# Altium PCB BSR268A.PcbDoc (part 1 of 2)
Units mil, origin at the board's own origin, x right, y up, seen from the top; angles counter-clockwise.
Board outline 3689.1 x 2409.61 mil, 4 copper layers (Top Layer, Signal Layer 1, Signal Layer 2, Bottom Layer), stack 60.312 mil thick; 90 components, 29 nets, 160 pads, 335 vias.
Unrouted connection lines stored in the file: 5.
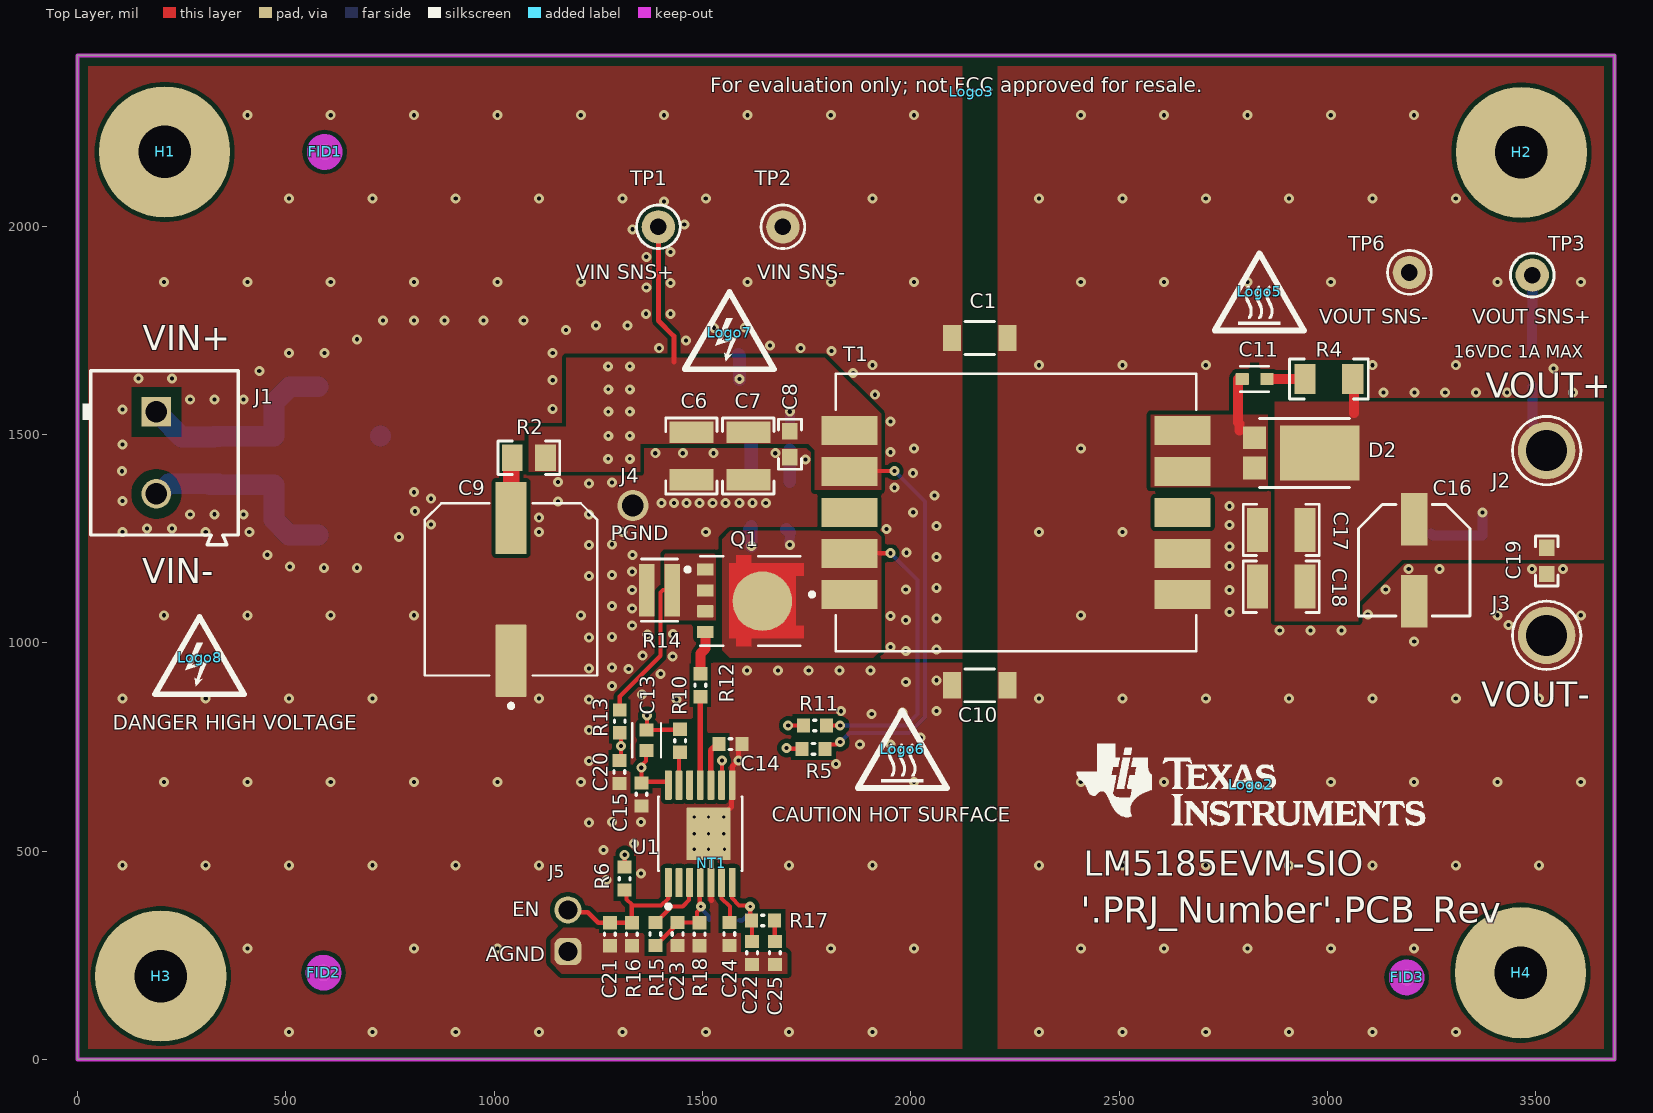
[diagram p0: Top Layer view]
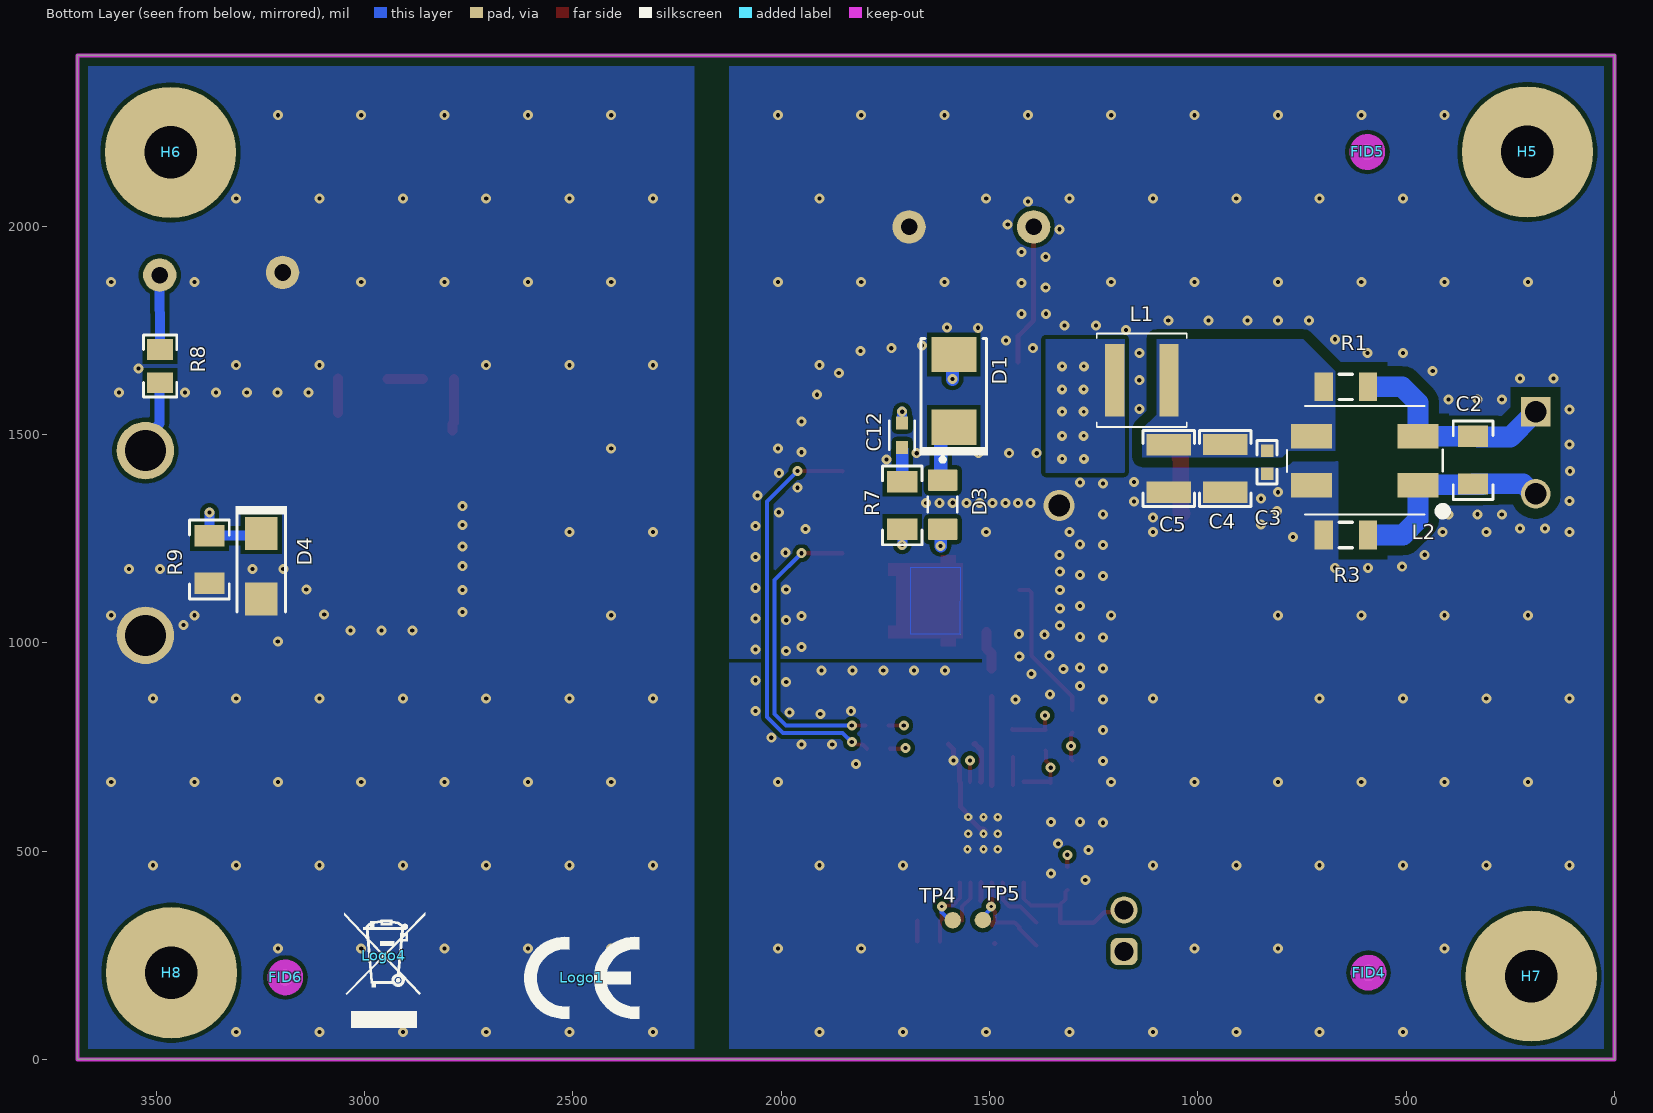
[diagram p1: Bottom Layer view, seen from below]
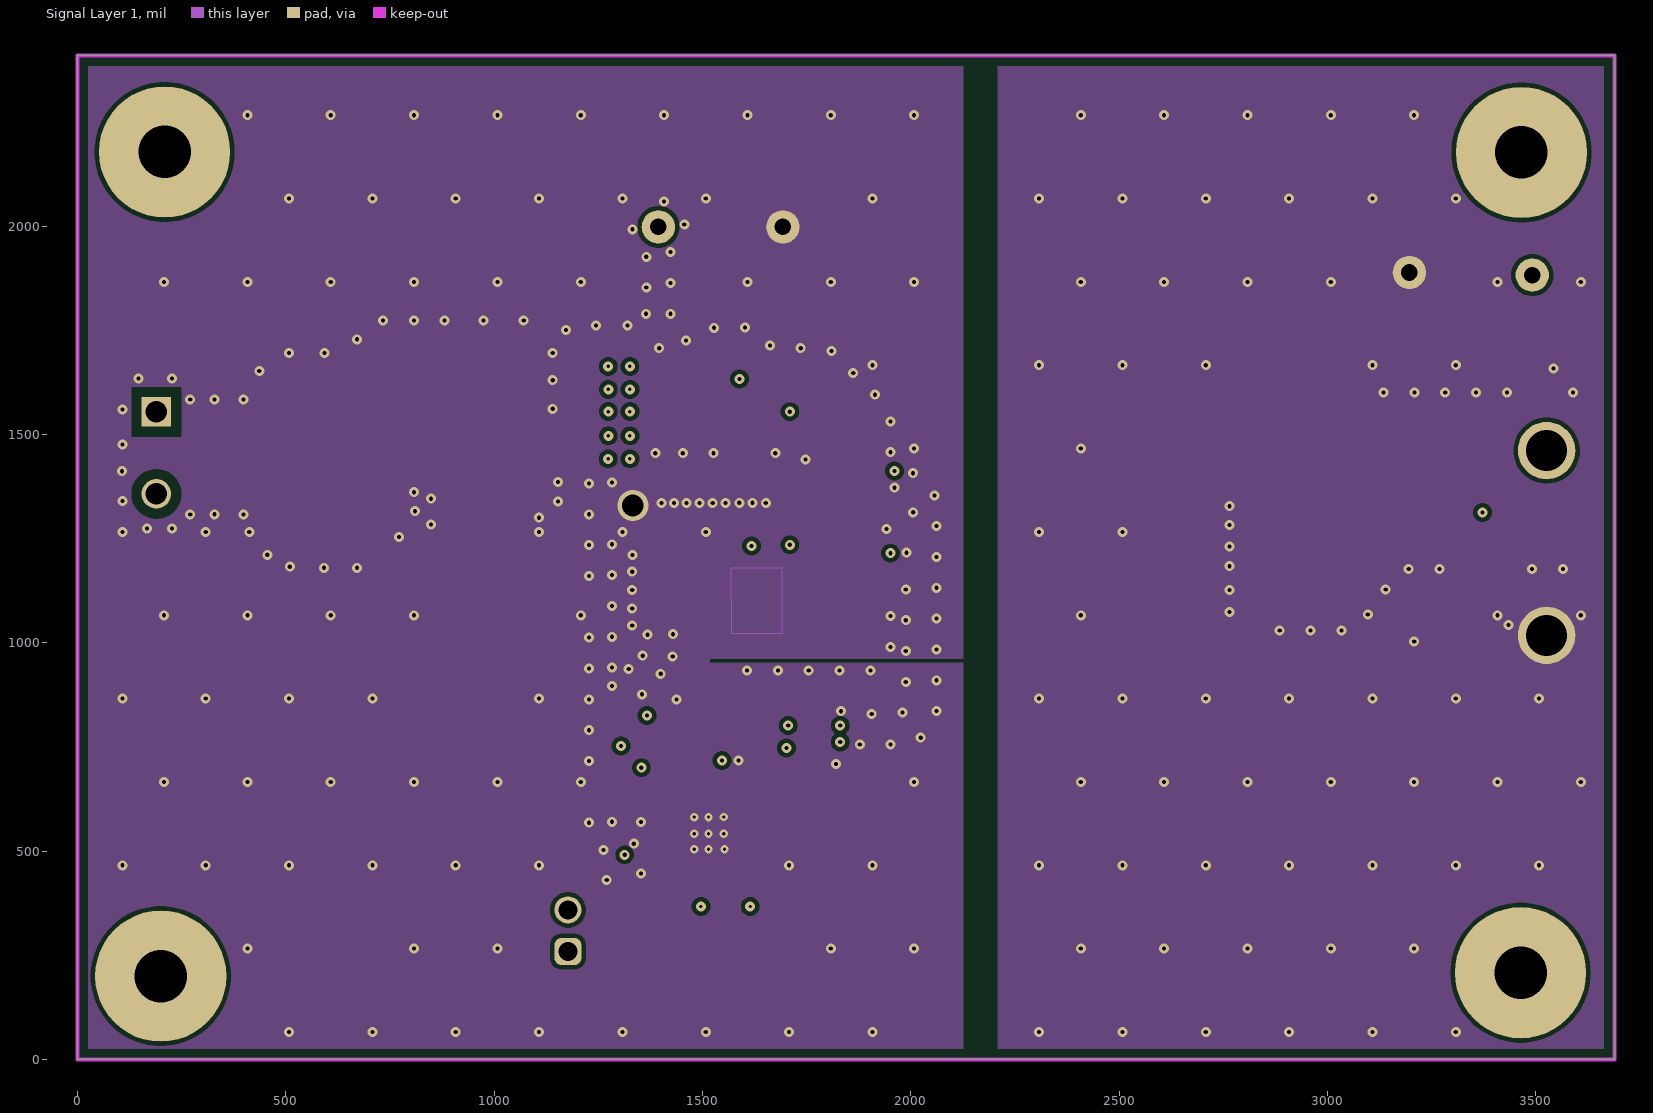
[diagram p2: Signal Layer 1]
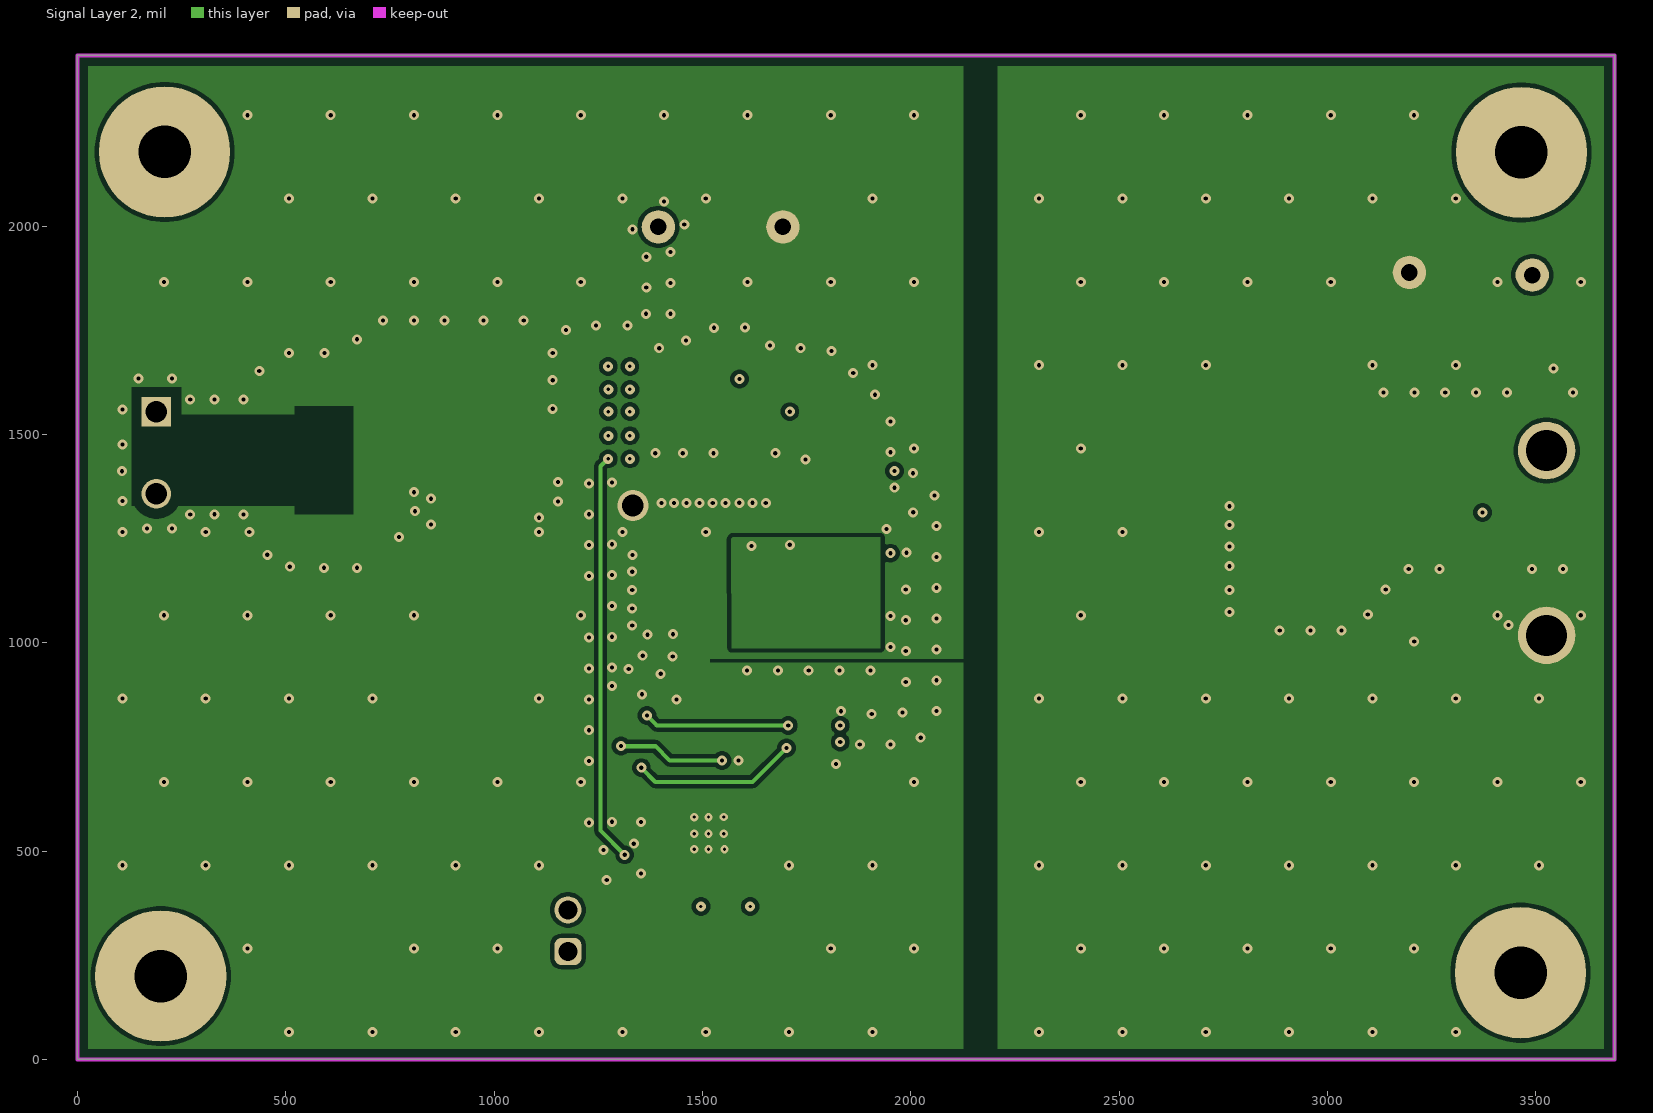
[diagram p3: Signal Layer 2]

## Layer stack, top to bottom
Top Solder: solder mask 0.4, Solder Resist, Dk 3.5
Top Layer: signal copper 2.7559
Dielectric 1: prepreg 8, FR-4 High Tg, Dk 4.1
Signal Layer 1: signal copper 1.4
Dielectric1: core 36, FR-4 High Tg, Dk 4.8
Signal Layer 2: signal copper 1.4
Dielectric 2: prepreg 8, FR-4 High Tg, Dk 4.1
Bottom Layer: signal copper 2.7559
Bottom Solder: solder mask 0.4, Solder Resist, Dk 3.5

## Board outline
0,0 3689.1,0 3689.1,2409.61 0,2409.61

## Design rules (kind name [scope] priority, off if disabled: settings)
AcuteAngle [All] p1: minimum=4.50000000000000E+0001 checktracksonly=FALSE
AssemblyTestPointUsage [All] p1: valid=2
BoardOutlineClearance BoardOutlineClearance_MountingHoles [OnCopper and InComponentClass('Mounting Holes')] p1: gap=39.37 ignorepadtopadclearanceinfootprint=FALSE
BoardOutlineClearance BoardOutlineClearance_Poly [OnCopper and IsPoly] p2: gap=25 ignorepadtopadclearanceinfootprint=FALSE
BoardOutlineClearance [OnCopper and Not InComponentClass('Logo') and not InComponentClass('FiducialMark') and not InRegion(1000,500,4000,800) and not InPoly] p3: gap=40 ignorepadtopadclearanceinfootprint=FALSE
Clearance Clearance_Keepouts [((IsTrack Or IsArc) And Not InPoly) And IsFree and IsKeepOut vs ((IsTrack Or IsArc) And Not InPoly) And IsFree and IsKeepOut] p1: gap=0 ignorepadtopadclearanceinfootprint=FALSE
Clearance Clearance_VIN_EMI [InNetClass('EMI_Net')] p2: gap=24 ignorepadtopadclearanceinfootprint=FALSE
Clearance Clearance_Poly [InPolygon] p3: gap=10 ignorepadtopadclearanceinfootprint=TRUE
Clearance Clearance_FiducialMark [IsKeepOut and InComponentClass('FiducialMark') vs IsPad and InComponentClass('FiducialMark')] p4: gap=0 ignorepadtopadclearanceinfootprint=FALSE
Clearance [All] p5: gap=7.87 ignorepadtopadclearanceinfootprint=TRUE
ComponentClearance ComponentClearance_MountingHoles_FiducialMarks [InComponentClass('Mounting Holes') vs InComponentClass('FiducialMark')] p1: gap=50 collisioncheckmode=3 verticalgap=10 showdistances=FALSE
ComponentClearance ComponentClearance_Shunt [InComponentClass('Header') vs InComponentClass('Shunt')] p2: gap=0 collisioncheckmode=3 verticalgap=0 showdistances=FALSE
ComponentClearance ComponentClearance_Logo [InComponentClass('Logo')] p3: gap=30 collisioncheckmode=3 verticalgap=10 showdistances=FALSE
ComponentClearance ComponentClearance_ScrewToNut [(HasFootprint('NY PMS 440 0025 PH')) vs (HasFootprint('Keystone_1902C'))] p4: gap=5 collisioncheckmode=3 verticalgap=10 showdistances=FALSE
ComponentClearance ComponentClearance_MountingHoles [InComponentClass('Mounting Holes')] p5: gap=100 collisioncheckmode=3 verticalgap=100000 showdistances=FALSE
ComponentClearance ComponentClearance_SmallPassives [HasFootprint('0201*') or HasFootprint('0402*') or HasFootprint('0508') or HasFootprint('0603*') or HasFootprint('0612') or HasFootprint('0805*') or HasFootprint('0815*') or HasFootprint('0830*') or HasFootprint('1206*') or HasFootprint('1210*') or HasFootprint('1808*') or HasFootprint('1812*') or HasFootprint('1825*') or HasFootprint('2010*') or HasFootprint('2220*') or HasFootprint('2225*') or HasFootprint('2512*') or HasFootprint('2728*') or HasFootprint('3518*') vs HasFootprint('0201*') or HasFootprint('0402*') or HasFootprint('0508') or HasFootprint('0603*') or HasFootprint('0612') or HasFootprint('0805*') or HasFootprint('0815*') or HasFootprint('0830*') or HasFootprint('1206*') or HasFootprint('1210*') or HasFootprint('1808*') or HasFootprint('1812*') or HasFootprint('1825*') or HasFootprint('2010*') or HasFootprint('2220*') or HasFootprint('2225*') or HasFootprint('2512*') or HasFootprint('2728*') or HasFootprint('3518*')] p6: gap=14.96 collisioncheckmode=3 verticalgap=10 showdistances=FALSE
ComponentClearance ComponentClearance_THtoSMT [IsThruComponent vs IsSMTComponent] p7: gap=30 collisioncheckmode=3 verticalgap=30 showdistances=FALSE
ComponentClearance ComponentClearance_THtoTH [IsThruComponent vs IsThruComponent] p8: gap=20 collisioncheckmode=3 verticalgap=30 showdistances=FALSE
ComponentClearance ComponentClearance_NetTie [HasFootprint('Net-Tie_10milWide_30milLong')] p9: gap=0 collisioncheckmode=3 verticalgap=0 showdistances=FALSE
ComponentClearance "ComponentClearance_CM Choke" [InComponent('R17') OR InComponent('R18') vs HasFootprint('IND_TDK_ACM7060')] p10: gap=0 collisioncheckmode=3 verticalgap=0 showdistances=FALSE
ComponentClearance [All] p11: gap=15 collisioncheckmode=3 verticalgap=10 showdistances=FALSE
DiffPairsRouting [All] p1: maxlimit=100 minlimit=10 mostfreqgap=10 toplayer_minwidth=15 toplayer_maxwidth=15 toplayer_prefwidth=15 midlayer1_minwidth=15 midlayer1_maxwidth=15 midlayer1_prefwidth=15 midlayer2_minwidth=15 midlayer2_maxwidth=15 midlayer2_prefwidth=15 bottomlayer_minwidth=15 bottomlayer_maxwidth=15 bottomlayer_prefwidth=15 maxuncoupledlength=1000
FabricationTestPointUsage TestPointUsage [All] p1: valid=2 allowmultiple=FALSE
FabricationTestpoint Testpoint [All] p1: side=3 testpointundercomponent=TRUE minsize=40 maxsize=100 preferedsize=60 minholesize=0 maxholesize=40 preferedholesize=32 testpointgrid=1 allowsidetop=TRUE allowsidebottom=TRUE usegrid=TRUE gridtolerance=0.01
FanoutControl Fanout_LCC [IsLCC] p1: bgadir=Out bgaviamode=Centered fanoutstyle=Auto fanoutdirection=Alternating viagrid=1 // Fanout_LCC (Default Rule)
FanoutControl Fanout_BGA [IsBGA] p2: bgadir=Out bgaviamode=Centered fanoutstyle=Auto fanoutdirection=Alternating viagrid=1 // Fanout_BGA (Default Rule)
FanoutControl Fanout_Default [All] p4: bgadir=Out bgaviamode=Centered fanoutstyle=Auto fanoutdirection=Alternating viagrid=1 // Fanout_Default (Default Rule)
FanoutControl Fanout_Small [(CompPinCount < 5)] p5: bgadir=Out bgaviamode=Centered fanoutstyle=Auto fanoutdirection=OutThenIn viagrid=1 // Fanout_Small (Default Rule)
HoleSize [All] p1: absolutevalues=TRUE maxlimit=251 minlimit=7.87 maxpercent=80.000 minpercent=20.000
MinimumAnnularRing MinimumAnnularRing_ThermalPadVias [IsVia and InAnyComponent] p1: minimumring=5.91
MinimumAnnularRing [All] p2: minimumring=6
MinimumSolderMaskSliver MinimumSolderMaskSliver_Logo [InComponentClass('Logo') vs InComponentClass('Logo')] p1: minsoldermaskwidth=0.7
MinimumSolderMaskSliver [All] p2: minsoldermaskwidth=3.94
PlaneConnect [All] p1: planeconnectstyle=Relief reliefexpansion=10 reliefentries=4 reliefconductorwidth=10 reliefairgap=10
PolygonConnect [All] p1: connectstyle=Direct reliefconductorwidth=10 reliefentries=4 polygonreliefangle="90 Angle" airgapwidth=10
RoutingVias ThermalPadVias [IsVia and InAnyComponent] p1: holewidth=7.87 width=19.68 viastyle="Through Hole" minholewidth=7.87 minwidth=19.68 maxholewidth=12.99 maxwidth=23.62
RoutingVias [All] p2: holewidth=16 width=34 viastyle="Through Hole" minholewidth=7.87 minwidth=20 maxholewidth=40 maxwidth=65
SilkToBoardRegionClearance [Not ((IsComment or IsDesignator) And (Hide <> 'False')) and not InRegion(1000,500,4000,800)] p1:
SilkToSilkClearance SilkToSilkClearance_Pb-FreeLogo [(HasFootprint('Pb-Free_Overlay_Medium') OR HasFootprint('Pb-Free_Overlay_Small')) vs (HasFootprint('Pb-Free_Overlay_Medium') OR HasFootprint('Pb-Free_Overlay_Small'))] p1: silktosilkclearance=0
SilkToSilkClearance [All] p2: silktosilkclearance=3.94
SilkToSolderMaskClearance SilkToComponentPadClearance_TSSOP16 [(IsPad or IsFill or IsRegion) and  HasFootprint('PWP0016A_N')] p1: minsilkscreentomaskgap=0 clearancetoexposedcopper=TRUE
SilkToSolderMaskClearance SilkToComponentPadClearance_SOD123 [(IsPad or IsFill or IsRegion) and HasFootprint('SOD-123') OR HasFootprint('SOD-123W')] p2: minsilkscreentomaskgap=3 clearancetoexposedcopper=TRUE
SilkToSolderMaskClearance SilkToComponentPadClearance [(IsPad or IsFill or IsRegion) and InAnycomponent] p3: minsilkscreentomaskgap=5 clearancetoexposedcopper=TRUE
SilkToSolderMaskClearance "Silk to Solder Mask Opening_TSSOP16" [HasFootprint('PWP0016A_N')] p4: minsilkscreentomaskgap=0 clearancetoexposedcopper=FALSE
SilkToSolderMaskClearance "Silk to Solder Mask Opening" [All] p5: minsilkscreentomaskgap=3.94 clearancetoexposedcopper=FALSE
SolderMaskExpansion [All] p1: expansion=1.97 istentingtop=FALSE
UnRoutedNet [All] p1: checkbadconnections=TRUE
Width [All] p1: maxlimit=100 minlimit=6 preferedwidth=10 checkconnectedcopper=TRUE
14 further rules are at their usual default settings.

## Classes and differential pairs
component class Header: J5
net class EMI_Net: NetC2_2 NetC3_1 VIN_EMI
component class "Mounting Holes": H1 H2 H3 H4
component class Logo: Logo2
component class FiducialMark: FID1 FID2 FID3 FID4 FID5 FID6
component class BSR268A_Hardware: !PCB1 FID1 FID2 FID3 FID4 FID5 FID6 H1 H2 H3 H4 H5 H6 H7 H8 Logo1 Logo2 Logo3 Logo4 Logo5 Logo6 Logo7 Logo8 ZZ1 ZZ2 ZZ3 ZZ4
component class AssemblyNote: ZZ1 ZZ2 ZZ3 ZZ4
component class BSR268A_BlankSheet: C1 C2 C3 C4 C5 C6 C7 C8 C9 C10 C11 C12 C13 C14 C15 C16 C17 C18 C19 C20 C21 C22 C23 C24 C25 D1 D2 D3 D4 J1 J2 J3 J4 J5 L1 L2 NT1 Q1 R1 R2 R3 R4 R5 R6 R7 R8 R9 R10 R11 R12 R13 R14 R15 R16 R17 R18 T1 TP1 TP2 TP3 TP4 TP5 TP6 U1

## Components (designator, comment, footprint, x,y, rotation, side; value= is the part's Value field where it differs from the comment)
C1 "202R18W102KV4E" 1206_190 2165.35,1731.3 r180 top value=1000pF
C2 "GRM319R72A104KA01D" 1206 339.68,1438.21 r270 bottom value=0.1uF
C3 "GRM188R72A104KA35D" 0603_HV 833.91,1433.34 r270 bottom value=0.1uF
C4 "C3225X7S2A475K200AB" 1210_220 934.52,1418.59 r270 bottom value=4.7uF
C5 "C3225X7S2A475K200AB" 1210_220 1070.02,1418.47 r270 bottom value=4.7uF
C6 "C3225X7S2A475K200AB" 1210_220 1473.69,1447.91 r270 top value=4.7uF
C7 "C3225X7S2A475K200AB" 1210_220 1610.38,1447.91 r270 top value=4.7uF
C8 "GRM188R72A104KA35D" 0603 1710.03,1476.4 r270 top value=0.1uF
C9 "865081757008" FP-865081757008_SMT_CAP_10MM3_10MM3-MFG 1040.7,1128.17 r90 top value=47µF
C10 "202R18W102KV4E" 1206_190 2165.35,898.01 r180 top value=1000pF
C11 "06031A151JAT2A" FP-06031A151JAT2A_0603-MFG 2825.02,1632.87 r0 top value=150pF
C12 "06031A151JAT2A" FP-06031A151JAT2A_0603-MFG 1709.93,1498.05 r90 bottom value=150pF
C13 "06031A101K4T2A" FP-06031A101K4T2A_0603-IPC_C 1365.93,766.18 r270 top
C14 "GRM188Z71C475KE21D" 0603L 1567.39,756.89 r0 top value=4.7uF
C15 "GRM188R72A104KA35D" 0603L 1353.84,636.18 r270 top value=0.1uF
C16 "EEE-FK1E101XP" SM_RADIAL_D8 3208.17,1197.83 r270 top value=100uF
C17 "GRM32ER71E226KE15L" 1210_270 2889.02,1270.67 r0 top value=22uF
C18 "GRM32ER71E226KE15L" 1210_270 2889.02,1134.84 r0 top value=22uF
C19 "GRM188R72A104KA35D" 0603 3525.97,1196.5 r270 top value=0.1uF
C20 "GRM1885C1H101JA01D" 0603L 1300.65,689.98 r270 top value=100pF
C21 "GCM1885C2A102JA16D" 0603L 1277.82,300.53 r270 top value=1000pF
C22 "CGA3E2NP01H470J080AA" 0603L 1619.2,255.7 r270 top value=47pF
C23 "C0603C104J4RACTU" 0603L 1440.45,301.13 r90 top value=0.1uF
C24 "C0603C104J4RACTU" 0603L 1564.76,301.13 r90 top value=0.1uF
C25 "C0603C223K3RACTU" 0603L 1673.65,255.7 r270 top value=0.022uF
D1 "SMBJ5362B-TP" SMB 1585.77,1604.69 r90 bottom value=28V
D2 "SDT5H100LP5-7" POWERDI5 2903.41,1455.71 r0 top value=100V
D3 "ACDBMT1100-HF" FP-ACDBMT1100-HF_SOD-123H-MFG 1612.48,1331.29 r270 bottom
D4 "SMAZ18-13-F" SMA 3248.03,1183.82 r270 bottom value=18V
FID1 "Fiducial" Fiducial10-20 593.33,2177.81 r0 top
FID2 "Fiducial" Fiducial10-20 590.55,208.18 r0 top
FID3 "Fiducial" Fiducial10-20 3190,196.85 r0 top
FID4 "Fiducial" Fiducial10-20 590.55,208.18 r180 bottom
FID5 "Fiducial" Fiducial10-20 593.33,2177.81 r180 bottom
FID6 "Fiducial" Fiducial10-20 3190,196.85 r180 bottom
H1 "NY PMS 440 0025 PH" "NY PMS 440 0025 PH" 209.35,2177.81 r0 top locked
H2 "NY PMS 440 0025 PH" "NY PMS 440 0025 PH" 3465.47,2176.67 r0 top locked
H3 "NY PMS 440 0025 PH" "NY PMS 440 0025 PH" 200,200 r0 top locked
H4 "NY PMS 440 0025 PH" "NY PMS 440 0025 PH" 3463.46,208.17 r0 top locked
H5 "1902C" Keystone_1902C 209.35,2177.81 r180 bottom locked
H6 "1902C" Keystone_1902C 3465.47,2176.67 r180 bottom locked
H7 "1902C" Keystone_1902C 200,200 r180 bottom locked
H8 "1902C" Keystone_1902C 3463.46,208.17 r180 bottom locked
J1 "691 101 710 002" Wurth_691101710002 189.35,1455.71 r270 top
J2 "1598-2" Keystone1598-2 3525.97,1461.15 r0 top
J3 "1598-2" Keystone1598-2 3525.97,1017.81 r90 top
J4 "1040" CONN_1040 1333.17,1329.39 r180 top
J5 "61300211121" WURTH_61300211121 1177.2,309.01 r90 top
L1 "XAL5050-223MEB" XAL5050 1134.68,1630.1 r0 bottom value=22uH
L2 "ACM70V-701-2PL-TL00" IND_TDK_ACM7060 599.51,1436.86 r0 bottom
Logo1 "CE Mark" CE_Mark_5mm 2478.85,195.51 r180 bottom
Logo2 "Texas Instruments" TI_Stacked_Overlay_Small 2816.22,659.45 r0 top
Logo3 "FCC disclaimer" FCC_disclaimer 2145.67,2322.83 r0 top
Logo4 "WEEE logo" WEEE_Minimum 2953.58,248.36 r180 bottom
Logo5 "CAUTION HOT SURFACE" IEC_HotSurface_Small 2836.48,1842.36 r0 top
Logo6 "CAUTION HOT SURFACE" IEC_HotSurface_Small 1979.63,744.09 r0 top
Logo7 "DANGER HIGH VOLTAGE" IEC_HighVoltage_Small 1564.59,1744.2 r0 top
Logo8 "DANGER HIGH VOLTAGE" IEC_HighVoltage_Small 293.25,964.57 r0 top
NT1 "Net-Tie" Net-Tie_10milWide_30milLong 1521.13,470.82 r90 top net-tie
Q1 "NVMFS021N10MCLT1G" FP-NVMFS021N10MCLT1G_DFN5-MFG 1615.02,1100.63 r270 top
R1 "ERJ-8GEY0R00V" 1206L 644.84,1614.21 r0 bottom value=0
R2 "RC0805FR-073R01L" 0805_HV 1083.68,1444.13 r180 top value=3.01
R3 "ERJ-8GEY0R00V" 1206L 644.84,1258.86 r0 bottom value=0
R4 "ERJ-8ENF1000V" 1206 3003.29,1632.87 r0 top value=100
R5 "RC0603FR-0710RL" 0603L 1766.65,745.51 r0 top value=10.0
R6 "RC0603FR-07200KL" 0603L 1313.44,434.06 r90 top value=200k
R7 "ERJ-8ENF1000V" 1206 1709.68,1329.7 r90 bottom value=100
R8 "ERJ-6GEY0R00V" 0805_HV 3490.72,1664.16 r90 bottom value=0
R9 "ERJ-8ENF3241V" 1206 3372.22,1199.8 r270 bottom value=3.24k
R10 "CRCW0603165KFKEA" 0603L 1446.36,764.82 r90 top value=165k
R11 "RC0603JR-071KL" 0603L 1769.86,801.52 r0 top value=1.0k
R12 "RC0603JR-070RL" 0603L 1494.9,898.01 r90 top value=0
R13 "RC0603FR-07100RL" 0603L 1301.53,811.52 r90 top value=100
R14 "PRL1632-R020-F-T1" 0612 1397.15,1126.38 r0 top value=0.02
R15 "RC0603FR-07294KL" 0603L 1387.05,301.13 r90 top value=294k
R16 "RC0603FR-0716K9L" 0603L 1330.51,300.53 r90 top value=16.9k
R17 "RC0603FR-0712K1L" 0603L 1645.11,333.61 r180 top value=12.1k
R18 "RC0603FR-0710KL" 0603L 1493.49,300.53 r90 top value=10.0k
T1 "ZD2250-AE" FP-ZD2250-AE_SMT10_21MM97_16MM9-MFG 2252.57,1312.69 r180 top
TP1 "5000" Keystone5000 1394.22,1998.03 r0 top
TP2 "5001" Keystone5001 1693.14,1998.03 r0 top
TP3 "5000" Keystone5000 3491.48,1882.37 r0 top
TP4 "TP_SM_1MM" TP_SM_1MM 1588.51,334.14 r180 bottom
TP5 "TP_SM_1MM" TP_SM_1MM 1516.1,334.48 r180 bottom
TP6 "5001" Keystone5001 3196.64,1888.78 r0 top
U1 "LM5185-Q1" NEU0014AA-MFG 1494.9,541.34 r90 top
ZZ1 "This Assembly Note is for PCB labels only" AssemblyNoteLabel 185,3938 r0 top
ZZ2 "These assemblies are ESD sensitive, ESD precautions shall be observed." AssemblyNote 185,3829.11 r0 top
ZZ3 "These assemblies must be clean and free from flux and all contaminants. Use of no clean flux is not acceptable." AssemblyNote 185,3740.56 r0 top
ZZ4 "These assemblies must comply with workmanship standards IPC-A-610 Class 2, unless otherwise specified." AssemblyNote 185,3652 r0 top

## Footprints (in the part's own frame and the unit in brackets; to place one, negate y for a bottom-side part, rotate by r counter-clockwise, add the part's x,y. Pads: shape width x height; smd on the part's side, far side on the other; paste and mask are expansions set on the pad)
0603 [mm] "0603 from SM-752 data"
  rect 1x0.95 smd: 1(-0.8,0) 2(0.8,0)
  silkscreen extent -1.52,-0.69 1.52,0.69, body extent -0.87,-0.47 0.87,0.47, height 1
0603_HV [mil] "Ernesto recommended land pattern.  26 mil between pads."
  rect 30x30 smd: 1(-28,0) 2(28,0)
  silkscreen extent -52,-24 52,24, body extent -34,-19 34,19, height 39
0603L [mm] "0603 from SM-752 data"
  rect 0.8x0.85 smd: 1(-0.7,0) 2(0.7,0)
  silkscreen extent -0.07,-0.33 0.07,0.33, body extent -0.87,-0.47 0.87,0.47, height 1
0612 [mm] "Panasonic recommended land pattern, fb97d03ed01.pdf dated April 2008"
  rect 0.95x3.2 smd: 1(-0.775,0) 2(0.775,0)
  silkscreen extent -1.1,-1.9 1.1,1.9, body extent -0.9,-1.7 0.9,1.7, height 0.85
0805_HV [mil] "0805 with 30mil clearance between pads"
  rect 50x63 smd: 1(-40,0) 2(40,0)
  silkscreen extent -74,-40 74,40, body extent -43,-29 43,29, height 57
1206 [mm] "1206 from SM-752 data"
  rect 1.3x1.85 smd: 1(-1.45,0) 2(1.45,0)
  silkscreen extent -2.4,-1.21 2.4,1.21, body extent -1.7,-0.9 1.7,0.9, height 1.35
1206_190 [mm] "1206_190"
  rect 1.1x1.6 smd: 1(-1.7,0) 2(1.7,0)
  silkscreen extent -0.9,-1 0.9,1, body extent -1.75,-0.95 1.75,0.95, height 1.9
1206L [mm] "1206 from SM-752 data"
  rect 1.1x1.75 smd: 1(-1.35,0) 2(1.35,0)
  silkscreen extent -0.4,-0.77 0.4,0.77, body extent -1.7,-0.9 1.7,0.9, height 1.35
1210_220 [mm] "1210"
  rect 1.3x2.7 smd: 1(-1.45,0) 2(1.45,0)
  silkscreen extent -2.32,-1.57 2.32,1.57, body extent -1.7,-1.35 1.7,1.35, height 2.2
1210_270 [mm] "1210"
  rect 1.3x2.7 smd: 1(-1.45,0) 2(1.45,0)
  silkscreen extent -2.32,-1.57 2.32,1.57, body extent -1.7,-1.35 1.7,1.35, height 2.7
AssemblyNote [mil] "Assembly Note"
AssemblyNoteLabel [mil] "Assembly Note for PCB Labels"
CE_Mark_5mm [mil] "Minimum text height for CE Mark"
  silkscreen extent -138,-98 138,98
CONN_1040 [mil] "Test Point, PC  test point Terminal"
  round 75 hole 52: 1(0,0)
  body extent -55,-12 55,13, height 276
FCC_disclaimer [mil]
Fiducial10-20 [mm]
  round 1 smd mask+0.5: 1(0,0)
  Top Layer keep-out circle w1.178: c0,0 r0.5
FP-06031A101K4T2A_0603-IPC_C [mil]
  rrect12% 31.75x34.18 smd paste+0 mask+0: 1(-24.64,0) 2(24.64,0)
  silkscreen extent -41,-35 41,35, body extent -44,-23 44,23, height 10
FP-06031A151JAT2A_0603-MFG [mm]
  rrect13% 0.8x0.75 smd paste+0 mask+0: 1(-0.75,0) 2(0.75,0)
  silkscreen extent -0.87,-0.77 0.87,0.77, body extent -1.25,-0.58 1.25,0.58, height 0.25
FP-865081757008_SMT_CAP_10MM3_10MM3-MFG [mm]
  rrect5% 4.4x1.9 smd paste+0 mask+0: 1(-4.35,0) 2(4.35,0)
  silkscreen extent -7.22,-5.25 5.25,5.25, body extent -6.8,-5.5 6.8,5.5, height 0.25
FP-ACDBMT1100-HF_SOD-123H-MFG [mm]
  rrect8% 1.3x1.8 smd paste+0 mask+0: 1(-1.5,0) 2(1.5,0)
  silkscreen extent -2.87,-0.9 0.48,0.9, body extent -1.75,-0.8 1.75,0.8, height 1
FP-NVMFS021N10MCLT1G_DFN5-MFG [mm]
  rrect13% 0.75x1 smd paste+0 mask+0: 1(-1.905,-2.748) 2(-0.635,-2.748) 3(0.635,-2.748) 4(1.905,-2.748)
  round 3.631 smd paste+0 mask+0: 5-6(0.021,0.735)
  Top Layer region: -2.28,-1.282 -2.28,-0.857 -2.775,-0.857 -2.775,0.048 -2.28,0.048 -2.28,3.247 -1.53,3.247 -1.53,2.772 1.53,2.772 1.53,3.247 2.28,3.247 2.28,0.048 2.775,0.048 2.775,-0.857 2.28,-0.857 2.28,-1.282
  silkscreen extent -2.73,-3.95 2.73,3.05, body extent -2.88,-3.35 2.88,3.35, height 0.25
FP-ZD2250-AE_SMT10_21MM97_16MM9-MFG [mm]
  rrect6% 3.43x1.79 smd paste+0 mask+0: 1(10.155,5) 2(10.155,2.5) 3(10.155,0) 4(10.155,-2.5) 5(10.155,-5) 6(-10.155,-5) 7(-10.155,-2.5) 8(-10.155,0) 9(-10.155,2.5) 10(-10.155,5)
  silkscreen extent -10.98,-8.45 12.56,8.45, body extent -11.97,-8.55 11.97,8.55, height 0.25
IEC_HighVoltage_Small [mil]
  silkscreen extent -107,-88 107,97
IEC_HotSurface_Small [mil]
  silkscreen extent -107,-93 107,92
IND_TDK_ACM7060 [mm] "TDK Common Mode EMI Filter 7mmx6mm"
  rect 2.5x1.5 smd: 1(-3.25,1.5) 2(-3.25,-1.5) 3(3.25,-1.5) 4(3.25,1.5)
  silkscreen extent -5,-3.32 4.75,3.32, body extent -3.6,-3.12 3.6,3.07, height 3.55
Keystone1598-2 [mm] "Triple Turret"
  round 3.5 hole 2.5: 1(0,0)
  silkscreen extent -2.08,-2.08 2.08,2.08, body extent -1.6,-1.6 1.59,1.6, height 7.72
Keystone5000 [mil] "For Keystone 500x miniature loop terminals"
  round 80 hole 40: 1(0,0)
  silkscreen extent -52,-52 52,52, body extent -49,-49 49,49, height 182
Keystone5001 [mil] "For Keystone 500x miniature loop terminals"
  round 80 hole 40: 1(0,0)
  silkscreen extent -52,-52 52,52, body extent -49,-49 49,49, height 182
Keystone_1902C [mil] "Hex Standoff, 4-40 threaded, nylon"
  round 1 on Mech4: 0(0,0)
  body extent -145,-126 146,126, height 501
Net-Tie_10milWide_30milLong [mil] "10mil net tie, no solder mask opening, no solder paste"
  rect 30x10 smd paste-5 mask-5: 1(-15,0) 2(15,0)
NEU0014AA-MFG [mm]
  rrect24% 1.78x0.42 smd paste+0 mask+0: 1(-2.97,1.95) 2(-2.97,1.3) 3(-2.97,0.65) 4(-2.97,0) 5(-2.97,-0.65) 6(-2.97,-1.3) 7(-2.97,-1.95) 8(2.97,-1.95) 9(2.97,-1.3) 10(2.97,-0.65) 11(2.97,0) 12(2.97,0.65) 13(2.97,1.3) 14(2.97,1.95)
  rrect4% 3.2x2.7 smd paste+0 mask+0: 15(0,-0.5)
  silkscreen extent -4.55,-2.55 2.25,2.55, body extent -3.96,-2.8 3.96,2.8, height 0.25
"NY PMS 440 0025 PH" [mm] "4-40 nylon screw and mounting hole"
  round 8 hole 3.2: 1(0,0)
  body extent -3.3,-3.3 3.3,3.3, height 2.69
POWERDI5 [mm] "Diodes Inc recommended land pattern, ap02001.pdf rev 60"
  rect 1.4x1.39 smd: 1(-1.991,0.92) 2(-1.991,-0.92)
  rect 4.86x3.36 smd: 3(1.991,0)
  silkscreen extent -1.7,-2.1 3.8,2.1, body extent -2.27,-2.03 4.33,2.03, height 1.17
SM_RADIAL_D8 [mm] "6.3 x 7.7mm:  Panasonic D8"
  rect 3.2x1.6 smd: 1(-2.5,0) 2(2.5,0)
  silkscreen extent -3.4,-3.4 3.4,3.4, body extent -3.4,-3.4 3.4,3.4, height 8.01
SMA [mm] "Molded Diode, 2-Leads, Body 4.3x2.6mm, IPC Medium Density, based on OnSemi component dimensions and land pattern"
  rect 2x2 smd: 1(-2,0) 2(2,0)
  silkscreen extent -3.66,-1.57 2.79,1.57, body extent -2.6,-1.3 2.6,1.3, height 2.42
SMB [mil] "Molded Diode, 2-Leads, Body 5.4x3.6mm, IPC Medium Density, based on OnSemi component dimensions"
  rect 85x107.99 smd: 1(-87.01,0) 2(87.01,0)
  silkscreen extent -155,-82 125,82, body extent -106,-71 106,71, height 91
TI_Stacked_Overlay_Small [mil]
  silkscreen extent -418,-98 418,98
TP_SM_1MM [mm] "1mm Test Point, SMT"
  round 1 smd paste-0.5: 1(0,0)
WEEE_Minimum [mil] "WEEElie bin"
  silkscreen extent -95,-172 99,104
WURTH_61300211121 [mm] "Header, 2.54mm, 2x1, TH"
  rrect50% 1.65x1.65 hole 1.15: 1(-1.27,0)
  round 1.65 hole 1.15: 2(1.27,0)
  body extent -2.54,-1.27 2.54,1.27, height 8.54
Wurth_691101710002 [mm] "Terminal Block, 5 mm, 2x1, TH"
  rect 1.8x1.8 hole 1.3: 1(-2.5,0)
  round 1.8 hole 1.3: 2(2.5,0)
  silkscreen extent -5,-4.5 5.6,5, body extent -5.6,-4 5.6,5, height 12.5
XAL5050 [mm] "CoilCraft XAL5050 5.28 x 5.48 x 5.1 mm"
  rect 1.18x4.44 smd: 1(-1.655,0) 2(1.655,0)
  silkscreen extent -2.75,-2.85 2.75,2.85, body extent -2.74,-2.84 2.74,2.84, height 5.1

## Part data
C1 C10: library part CMP-0008572-2, "CAP, CERM, 1000 pF, 2000 V, +/- 10%, X7R, 1206_190", Cap_Case=1206, Manufacturer="Johanson Technology", TempCo=X7R, Tolerance_%=10%, Value1=Unknown, Value2=2000V, ValueDisplayed=1000pF
C2: library part CMP-0008881-2, "CAP, CERM, 0.1 uF, 100 V, +/- 10%, X7R, 1206", Cap_Case=1206, Manufacturer=MuRata, Supplier Part Number 1=490-3364-1-ND, TempCo=X7R, Tolerance_%=10%, Value1=Unknown, Value2=100V, ValueDisplayed=0.1uF
C3 C8 C15 C19: library part CMP-0007469-4, "CAP, CERM, 0.1 uF, 100 V, +/- 10%, X7R, 0603", Cap_Case=0603, Manufacturer=MuRata, Supplier Part Number 1=490-3285-1-ND, TempCo=X7R, Tolerance_%=10%, Value1=Unknown, Value2=100V, ValueDisplayed=0.1uF
C4 C5 C6 C7: library part CMP-0009134-2, "CAP, CERM, 4.7 uF, 100 V, +/- 10%, X7S, 1210", Cap_Case=1210_220, Manufacturer=TDK, Supplier Part Number 1=445-6042-1-ND, TempCo=X7S, Tolerance_%=10%, Value1="0.004236 ohm", Value2=100V, ValueDisplayed=4.7uF
C9: library part CMP-0095714-1, "Aluminum Electrolytic Capacitor 47uF 20% 80V 10.3x10.3x10.5mm SMT", Leakage Current=37.6uA, Manufacturer="Wurth Electronics", Operating Temperature Range="-55°C to +105°C", Tolerance_%=20%, ValueDisplayed=47uF
C11 C12: library part CMP-0096650-1, "0603 150 pF 100 V ±5 % Tolerance C0G/NP0 SMT Multilayer Ceramic Capacitor", Digikey Part Number=478-1147-1-ND, Manufacturer="KYOCERA AVX", Mouser Part Number=581-06031A151J, Operating Temperature Range="-55°C to +125°C", TempCo=30ppm/°C, Temperature Characteristic=C0G, Tolerance_%=5%, ValueDisplayed=150pF
C13: library part CMP-0089170-1, "100pF ±10% 100V Ceramic Capacitor C0G, NP0 0603 (1608 Metric)", Digikey Part Number=478-9853-1-ND, Manufacturer=AVX, Mouser Part Number=581-06031A101K4T2A, Operating Temperature Range="-55°C to +125°C", TempCo=30ppm/°C, Temperature Characteristic=NP0, Tolerance_%=10%, ValueDisplayed=100pF
C14: library part CMP-0064936-4, "CAP, CERM, 4.7 uF, 16 V,+/- 10%, X7R, 0603", Cap_Case=0603, Manufacturer=MuRata, TempCo=X7R, Tolerance_%=10%, Value1=Unknown, Value2=16V, ValueDisplayed=4.7uF
C16: library part CMP-0010711-1, "CAP, AL, 100 uF, 25 V, +/- 20%, 0.34 ohm, AEC-Q200 Grade 2, SMD", Cap_Case=D8, Manufacturer=Panasonic, Supplier Part Number 1=PCE3797CT-ND, Tolerance_%=20%, Value1="0.34 ohm", Value2=25V, ValueDisplayed=100uF
C17 C18: library part CMP-0009224-2, "CAP, CERM, 22 uF, 25 V, +/- 10%, X7R, 1210", Cap_Case=1210, Manufacturer=MuRata, Supplier Part Number 1=490-5313-1-ND, TempCo=X7R, Tolerance_%=10%, Value1=Unknown, Value2=25V, ValueDisplayed=22uF
C20: library part CMP-0007171-4, "CAP, CERM, 100 pF, 50 V, +/- 5%, C0G/NP0, 0603", Cap_Case=0603, Manufacturer=MuRata, Supplier Part Number 1=490-1427-1-ND, TempCo=C0G/NP0, Tolerance_%=5%, Value1=Unknown, Value2=50V, ValueDisplayed=100pF
C21: library part CMP-0007131-4, "CAP, CERM, 1000 pF, 100 V, +/- 5%, C0G/NP0, AEC-Q200 Grade 1, 0603", Cap_Case=0603, Manufacturer=MuRata, Supplier Part Number 1=490-4772-1-ND, TempCo=C0G/NP0, Tolerance_%=5%, Value1=Unknown, Value2=100V, ValueDisplayed=1000pF
C22: library part CMP-0080062-1, "CAP, CERM, 47 pF, 50 V,+/- 5%, C0G/NP0, AEC-Q200 Grade 0, 0603", Cap_Case=0603, Manufacturer=TDK, Supplier Part Number 1=445-12417-1-ND, TempCo=C0G/NP0, Tolerance_%=5%, Value2=50V, ValueDisplayed=47pF
C23 C24: library part CMP-0006857-4, "CAP, CERM, 0.1 uF, 16 V, +/- 5%, X7R, 0603", Cap_Case=0603, Manufacturer=Kemet, Supplier Part Number 1=399-1097-1-ND, TempCo=X7R, Tolerance_%=5%, Value1=Unknown, Value2=16V, ValueDisplayed=0.1uF
C25: library part CMP-0006899-4, "CAP, CERM, 0.022 uF, 25 V, +/- 10%, X7R, 0603", Cap_Case=0603, Manufacturer=Kemet, Supplier Part Number 1=399-1094-1-ND, TempCo=X7R, Tolerance_%=10%, Value1=Unknown, Value2=25V, ValueDisplayed=0.022uF
D1: library part CMP-0005655-4, "Diode, Zener, 28 V, 5 W, SMB", Manufacturer="Micro Commercial Components", Power_W=5W
D2: library part CMP-0077681-2, "Diode, Schottky, 100 V, 5 A, PowerDI5", Manufacturer="Diodes Inc.", Value1=5A, Value2=0.66V
D3: library part CMP-0098302-1, "Diode 100 V 1A Surface Mount SOD-123H", Digikey Part Number=641-1610-1-ND, Forward Current=1A, Manufacturer="Comchip Technology", Max Surge Forward Current=30A, Mouser Part Number=750-ACDBMT1100-HF, Operating Temperature Range="-55°C to +150°C", Peak Reverse Current=0.5mA, ValueDisplayed=120pF
D4: library part CMP-0005526-4, "Diode, Zener, 18 V, 1 W, AEC-Q101, SMA", Manufacturer="Diodes Inc.", Power_W=1W
FID1 FID2 FID3 FID4 FID5 FID6: library part CMP-0077181-1, "Fiducial mark.  There is nothing to buy or mount.", Manufacturer=N/A
H1 H2 H3 H4: library part CMP-0003617-1, "Machine Screw, Round, #4-40 x 1/4, Nylon, Philips panhead", Manufacturer="B&F Fastener Supply", Supplier Part Number 1=H542-ND
H5 H6 H7 H8: library part CMP-0003610-1, "Standoff, Hex, 0.5\"L #4-40 Nylon", Manufacturer=Keystone, Supplier Part Number 1=36-1902C-ND
J1: library part CMP-0054828-1, "Terminal Block, 5 mm, 2x1, Tin, TH", Manufacturer="Wurth Elektronik", Supplier Part Number 1=732-2026-ND
J2 J3: library part CMP-0055121-1, "Terminal, Turret, TH, Triple", Manufacturer=Keystone, Supplier Part Number 1=36-1598-2-ND
J4: library part CMP-0055161-1, Manufacturer=Keystone, Supplier Part Number 1=36-1040-ND
J5: library part CMP-0054794-2, "Header, 2.54 mm, 2x1, Gold, TH", Color=Black, Manufacturer="Wurth Elektronik", Supplier Part Number 1=732-5315-ND
L1: library part CMP-0061651-2, "Inductor, Shielded, Composite, 22 uH, 3.4 A, 0.1 ohm, SMD", Manufacturer=Coilcraft, Value1="0.1 ohm", Value2=3.4A, ValueDisplayed=22uH
L2: library part CMP-0085405-1, "Coupled inductor, 0.015 ohm, AEC-Q200 Grade 1, SMD", Manufacturer=TDK
Logo1: library part CMP-0074844-1
Logo2: library part CMP-0074838-1, "Texas Instrument Corporate Signature"
Logo3: library part CMP-0074847-1, "FCC_disclaimer"
Logo4: library part CMP-0074769-3, Manufacturer="Texas Instruments"
Logo5 Logo6: library part CMP-0074837-2, "IEC 61010-1 Hot Surface Warning", Manufacturer="Texas Instruments"
Logo7 Logo8: library part CMP-0074835-1, "IEC 61010-1 High Voltage Warning"
NT1: library part CMP-0078142-6, "Single point connection between nets.", Manufacturer=N/A
Q1: library part CMP-0032635-1, "N-Channel 100 V 8.4A (Ta), 31A (Tc) 3.6W (Ta), 49W (Tc) Surface Mount 5-DFN (5x6) (8-SOFL)", Digikey Part Number=488-NVMFS021N10MCLT1GCT-ND, Drain To Source Breakdown Voltage=100V, Input Capacitace At Vds="850pF @ 50V", Manufacturer=onsemi, Mouser Part Number=863-MFS021N10MCLT1G, Operating Temperature Range="-55°C to +175°C", Power_W=3.6W, Pulse Drain Current=159A, Typ Forward Diode Voltage=0.83V
R1 R3: library part CMP-0018748-3, "RES, 0, 5%, 0.25 W, AEC-Q200 Grade 0, 1206", Manufacturer=Panasonic, Power_W=250mW, Supplier Part Number 1=P0.0ECT-ND, TempCo="600 ppm/C", Tolerance_%=5%, Value2=0.25W, Value_Code=0000, ValueDisplayed=0
R2: library part CMP-0021914-2, "RES, 3.01, 1%, 0.125 W, 0805", Manufacturer="Yageo America", Power_W=125mW, Supplier Part Number 1=311-3.01CRCT-ND, TempCo="200 ppm/C", Tolerance_%=1%, Value2=0.125W, Value_Code=3R01, ValueDisplayed=3.01
R4 R7: library part CMP-0017282-3, "RES, 100, 1%, 0.25 W, AEC-Q200 Grade 0, 1206", Manufacturer=Panasonic, Power_W=250mW, Supplier Part Number 1=P100FCT-ND, TempCo="100 ppm/C", Tolerance_%=1%, Value2=0.25W, Value_Code=100R, ValueDisplayed=100
R5: library part CMP-0022751-4, "RES, 10.0, 1%, 0.1 W, 0603", Manufacturer=Yageo, Power_W=100mW, Supplier Part Number 1=311-10.0HRCT-ND, TempCo="100 ppm/C", Tolerance_%=1%, Value2=0.1W, Value_Code=10R0, ValueDisplayed=10.0
R6: library part CMP-0022901-4, "RES, 200 k, 1%, 0.1 W, 0603", Manufacturer=Yageo, Power_W=100mW, Supplier Part Number 1=311-200KHRCT-ND, TempCo="100 ppm/C", Tolerance_%=1%, Value2=0.1W, Value_Code=200k
R8: library part CMP-0020616-3, "RES, 0, 5%, 0.125 W, AEC-Q200 Grade 0, 0805", Manufacturer=Panasonic, Power_W=125mW, Supplier Part Number 1=P0.0ACT-ND, TempCo="600 ppm/C", Tolerance_%=5%, Value2=0.125W, Value_Code=0000, ValueDisplayed=0
R9: library part CMP-0017537-3, "RES, 3.24 k, 1%, 0.25 W, AEC-Q200 Grade 0, 1206", Manufacturer=Panasonic, Power_W=250mW, Supplier Part Number 1=P3.24KFCT-ND, TempCo="100 ppm/C", Tolerance_%=1%, Value2=0.25W, Value_Code=3k24, ValueDisplayed=3.24k
R10: library part CMP-0022075-4, "RES, 165 k, 1%, 0.1 W, AEC-Q200 Grade 0, 0603", Manufacturer=Vishay-Dale, Power_W=100mW, Supplier Part Number 1=541-165KHCT-ND, TempCo="100 ppm/C", Tolerance_%=1%, Value2=0.1W, Value_Code=165k
R11: library part CMP-0025899-5, "RES, 1.0 k, 5%, 0.1 W, 0603", Manufacturer=Yageo, Power_W=100mW, Supplier Part Number 1=311-1.0KGRCT-ND, TempCo="100 ppm/C", Tolerance_%=5%, Value2=0.1W, Value_Code=1k00, ValueDisplayed=1.0k
R12: library part CMP-0025885-5, "RES, 0, 5%, 0.1 W, 0603", Manufacturer=Yageo, Power_W=100mW, Supplier Part Number 1=311-0.0GRCT-ND, TempCo="200 ppm/C", Tolerance_%=5%, Value2=0.1W, Value_Code=0000, ValueDisplayed=0
R13: library part CMP-0022736-4, "RES, 100, 1%, 0.1 W, 0603", Manufacturer=Yageo, Power_W=100mW, Supplier Part Number 1=311-100HRCT-ND, TempCo="100 ppm/C", Tolerance_%=1%, Value2=0.1W, Value_Code=100R, ValueDisplayed=100
R14: library part CMP-0015215-3, "RES, 0.02, 1%, 1 W, 0612", Manufacturer="Susumu Co Ltd", Power_W=1W, Supplier Part Number 1=PRL1632.020FCT-ND, TempCo="100 ppm/C", Tolerance_%=1%, Value_Code=R020, ValueDisplayed=0.02
R15: library part CMP-0022977-4, "RES, 294 k, 1%, 0.1 W, 0603", Manufacturer=Yageo, Power_W=100mW, Supplier Part Number 1=311-294KHRCT-ND, TempCo="100 ppm/C", Tolerance_%=1%, Value2=0.1W, Value_Code=294k
R16: library part CMP-0022830-5, "RES, 16.9 k, 1%, 0.1 W, 0603", Manufacturer=Yageo, Power_W=100mW, Supplier Part Number 1=311-16.9KHRCT-ND, TempCo="100 ppm/C", Tolerance_%=1%, Value2=0.1W, Value_Code=16k9, ValueDisplayed=16.9k
R17: library part CMP-0022776-5, "RES, 12.1 k, 1%, 0.1 W, 0603", Manufacturer=Yageo, Power_W=100mW, Supplier Part Number 1=311-12.1KHRCT-ND, TempCo="100 ppm/C", Tolerance_%=1%, Value2=0.1W, Value_Code=12k1, ValueDisplayed=12.1k
R18: library part CMP-0022746-5, "RES, 10.0 k, 1%, 0.1 W, 0603", Manufacturer=Yageo, Power_W=100mW, Supplier Part Number 1=311-10.0KHRCT-ND, TempCo="100 ppm/C", Tolerance_%=1%, Value2=0.1W, Value_Code=10k0, ValueDisplayed=10.0k
T1: library part CMP-0097601-1, "EFD15 10PIN SMD FLYBACK TRANSFORMER", Manufacturer=Coilcraft, Operating Temperature Range=to, Voltage_Isolation_Vrms=2000Vrms
TP1 TP3: library part CMP-0055137-2, "Test Point, Miniature, Red, TH", Color=Red, Manufacturer="Keystone Electronics", Supplier Part Number 1=36-5000-ND
TP2 TP6: library part CMP-0055138-2, "Test Point, Miniature, Black, TH", Color=Black, Manufacturer="Keystone Electronics", Supplier Part Number 1=36-5001-ND
TP4 TP5: library part CMP-0003825-1, "1mm Test Point, SMT", Manufacturer=Any
U1: library part CMP-0091530-1, "120-VIN PSR Flyback Automotive DC/DC Controller With Low IQ and Low EMI, HTSSOP14", Manufacturer="Texas Instruments", Max Supply Voltage=120V, Min Supply Voltage=4.5V, Operating Temperature Range="-40°C to +150°C"
ZZ1: library part CMP-0003616-3
ZZ2: library part CMP-0077236-1
ZZ3: library part CMP-0077237-1
ZZ4: library part CMP-0077238-1

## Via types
v1: diameter 24, hole 10, Top Layer to Bottom Layer, tented both sides, 314 vias
v2: diameter 24, hole 8, Top Layer to Bottom Layer, tented both sides, 12 vias
v3: diameter 20, hole 8, Top Layer to Bottom Layer, tented both sides, 9 vias

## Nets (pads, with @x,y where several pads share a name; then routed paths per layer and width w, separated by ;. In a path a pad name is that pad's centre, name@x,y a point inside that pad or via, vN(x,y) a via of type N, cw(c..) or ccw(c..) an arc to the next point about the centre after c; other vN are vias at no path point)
AGND: C21.2 C22.2 C23.1 C24.1 C25.2 J5.1 NT1.1 R16.1 R18.1 U1.5 | length 44.2
  Top Layer w12: R18.1@1486.8,278.49 R18.1@1487.78,278.49 ; U1.5@1520.49,424.41 1520.65,424.25 1520.65,383.23 1522.05,381.83
ISO-GND: C1.1 C10.1 C16.2 C17.1 C18.1 C19.2 D4.2 J3.1 R9.2 T1.9 T1.10 TP6.1
  other v1: 2308,66 2508,66 2708,66 2908,66 3108,66 3308,66 2408,266 2608,266 2808,266 3008,266 3208,266 2308,466 2508,466 2708,466 2908,466 3108,466 3308,466 3508,466 2408,666 2608,666 2808,666 3008,666 3208,666 3408,666 3608,666 2308,866 2508,866 2708,866 2908,866 3108,866 3308,866 3508,866 3208.17,1002.95 2885.33,1029.73 2959.33,1029.73 3033.33,1029.73 3434.55,1042.32 2408,1066 3408,1066 3608,1066 3096.74,1067.88 2765.26,1073.82 2765.26,1126.73 3139.81,1128.06 3194.98,1177.37 3268.98,1177.37 3490.98,1177.37 3564.98,1177.37 2765.26,1183.82 2765.26,1231.06 2308,1266 2508,1266 2765.26,1282.24 2765.26,1327.81 2408,1466 3134.55,1600.78 3208.55,1600.78 3282.55,1600.78 3356.55,1600.78 3430.55,1600.78 3588.92,1600.78 3542.52,1658.42 2308,1666 2508,1666 2708,1666 3108,1666 3308,1666 2408,1866 2608,1866 2808,1866 3008,1866 3408,1866 3608,1866 2308,2066 2508,2066 2708,2066 2908,2066 3108,2066 3308,2066 2408,2266 2608,2266 2808,2266 3008,2266 3208,2266
NetC2_2: C2.2 J1.2 L2.1 R3.1 | length 517.9
  Bottom Layer w50: J1.2@189.35,1357.28 195,1357.28 219.38,1381.66 C2.2@339.14,1381.66 ; C2.2@317.49,1379.96 339.67,1379.73 L2.1@471.56,1378.32 ; L2.1@471.56,1377.8 471.56,1295.3 508,1258.86 R3.1@577.91,1258.86
NetC3_1: C3.1 C4.1 C5.1 L1.1 L2.3 R1.2 | length 0.3
  Bottom Layer w50: L2.3@727.28,1496.1 L2.3@727.46,1495.91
